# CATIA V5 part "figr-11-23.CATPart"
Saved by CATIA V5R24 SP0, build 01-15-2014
Part number: Part1
Bounding box of the stored display mesh (mm): x -89.703 to 75.958, y -127.286 to 108.862, z -26.487 to 19.815
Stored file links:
  D:\KAVITA\CATIA V5-6R2014 Project_ Kavita\CATIA V5-6R2014_partfiles\Partfiles\c11_catia_v5-6r2014_prt\figr-11-23.CATPart
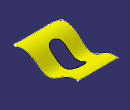
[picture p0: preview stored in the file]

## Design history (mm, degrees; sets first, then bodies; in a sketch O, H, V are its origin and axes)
Set1
  Extrude1: Element1 Sketch3, Lim1 86, Lim2 94, Direction yz-plane
  Sketch1 on xy-plane, origin (0, 0, 0), H (1, 0, 0), V (0, 1, 0)
    line L1 (64.3059, 108.8616) -> (75.9293, -106.0218)
    arc A1 centre (55.7837, -107.1115) radius 20.175 from (75.9293, -106.0218) to (55.7837, -127.2865) cw
    line L2 (55.7837, -127.2865) -> (-64.7868, -127.2865)
    arc A2 centre (-64.7868, -102.3613) radius 24.9252 from (-64.7868, -127.2865) to (-89.6873, -101.2501) cw
    line L3 (-89.6873, -101.2501) -> (-80.3115, 108.8616)
    line L4 (-80.3115, 108.8616) -> (64.3059, 108.8616)
    tangency: A1 L1, A2 L2, A2 L3, A1 L2
    horizontal: L2 H, L4 H
  Extrude2: Element1 Sketch1, Lim1 86, Lim2 94, Direction xy-plane
  Split1: ToCut Extrude1, Cutting Extrude2
  Sketch2 on xy-plane, origin (0, 0, 0), H (1, 0, 0), V (0, 1, 0)
    construction line L1 (-11.3849, 28.4134) -> (-11.3849, -36.9379)
    line L2 (12.8382, 28.4134) -> (12.8382, -36.9379)
    line L3 (-35.608, -36.9379) -> (-35.608, 28.4134)
    arc A1 centre (-11.3849, -36.9379) radius 24.2231 from (12.8382, -36.9379) to (-35.608, -36.9379) cw
    arc A2 centre (-11.3849, 28.4134) radius 24.2231 from (-35.608, 28.4134) to (12.8382, 28.4134) cw
    vertical: L1 V
    tangency: A1 L2, A2 L2, A1 L3, A2 L3
    parallelism: L1 L2
  Extrude3: Element1 Sketch2, Lim1 86, Lim2 94, Direction xy-plane
  Split2: ToCut Split1, Cutting Extrude3
  Boundary1: Boundary edge of Split2, Support Split2
Body1 (main body)
  Sketch3 on yz-plane, origin (0, 0, 0), H (0, 1, 0), V (0, 0, 1)
    spline S1 through (-130.9721, 0) (-85.5087, 19.8151) (-38.0512, 0) (0, -25.6483) (60.0541, -1.7202) (134.7951, -4.3868)
    point P1 (-130.9721, 0)
    point P2 (-38.0512, 0)
    point P3 (0, -25.6483)
    coincidence: P1 H, P2 H, P3 V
